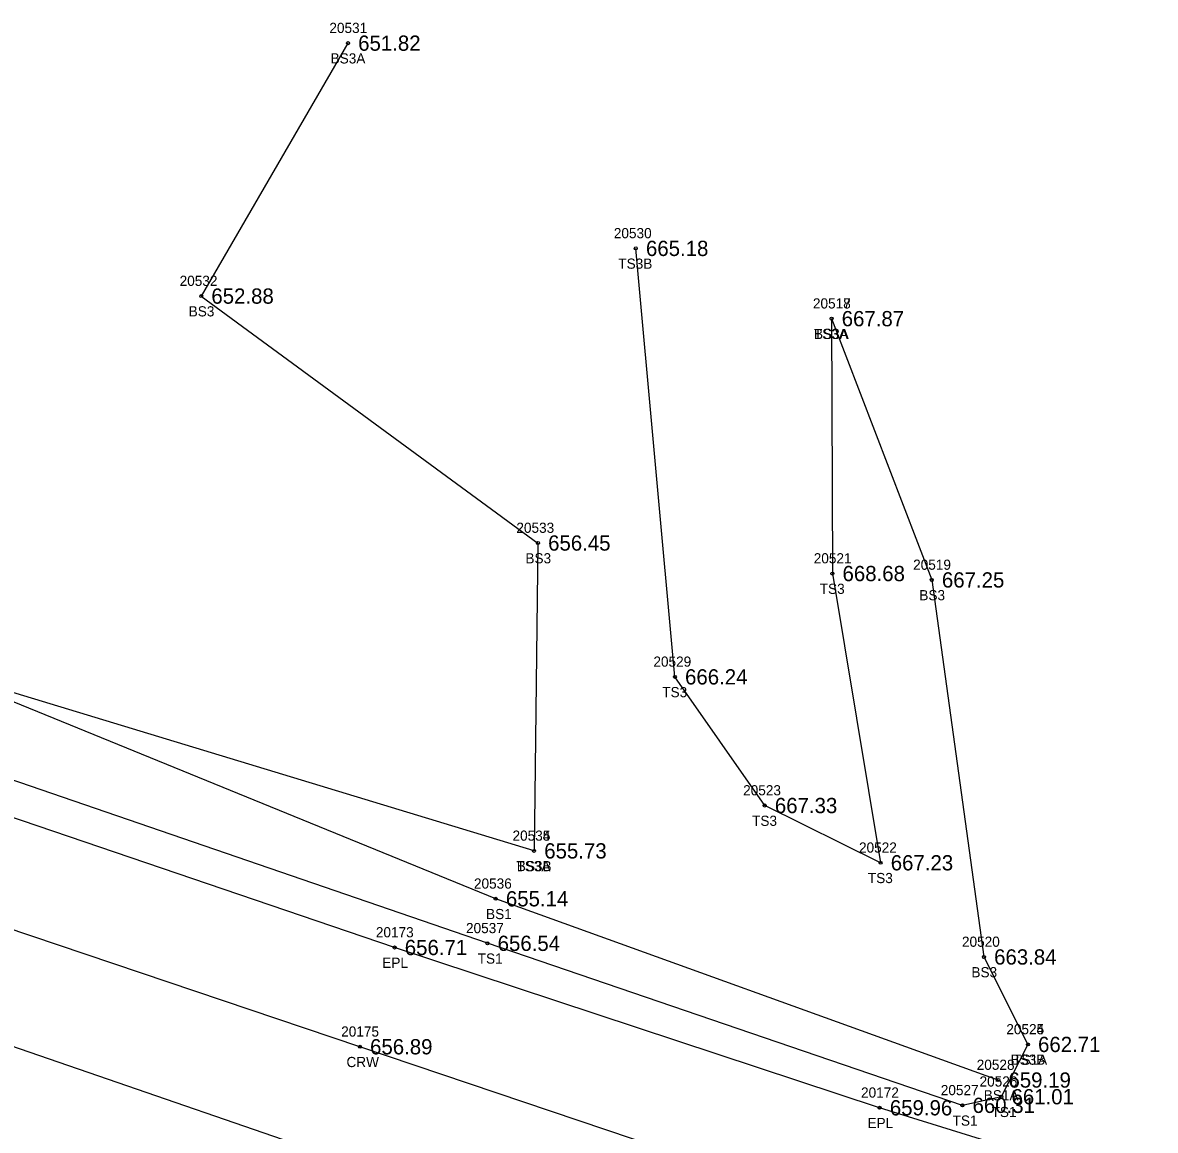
# Model space of a CAD drawing. Extents: x 1655675 to 1657082, y 1004080 to 1005193.
# Drawn here: x 1656444.9 to 1656556.3, y 1004582.5 to 1004691.4 of the extents above; entities that cross this region are included whole.
import ezdxf

# ---------------------------------------------------------------- set-up
doc = ezdxf.new("R2010")
doc.units = 0
for name, color, linetype in [('RD_DTM_BkLn1', 7, 'Continuous'), ('RD_DTM_BkLn2', 7, 'Continuous'), ('RD_DTM_BkLn_txCode', 7, 'Continuous'), ('RD_EX_Road', 7, 'Continuous'), ('RD_EX_Road_txCode', 7, 'Continuous'), ('RD_EX_TX_Misc_ELEV', 7, 'Continuous'), ('RD_EX_TX_Road_ELEV', 7, 'Continuous'), ('RD_HC_Survey_ELEV', 7, 'Continuous'), ('RD_HC_Survey_txCode', 7, 'Continuous'), ('RD_SMD_Locator', 7, 'Continuous')]:
    doc.layers.add(name, color=color, linetype=linetype)

msp = doc.modelspace()

# ---------------------------------------------------------------- linework, layer by layer
at = {"layer": 'RD_DTM_BkLn1'}
msp.add_lwpolyline([(1657061.44, 1004399.53), (1657012.07, 1004414.01), (1656963.11, 1004429.39), (1656914.21, 1004444.93), (1656865.73, 1004460.97), (1656817.07, 1004476.94), (1656768.62, 1004493.15), (1656720.24, 1004509.39), (1656671.72, 1004525.86), (1656623.45, 1004542.51), (1656574.61, 1004558.72), (1656526.43, 1004574.41), (1656478.09, 1004590.75), (1656429.6, 1004607.09), (1656401.58, 1004616.48)], dxfattribs=at)
at = {"layer": 'RD_DTM_BkLn2'}
msp.add_line((1656495.21, 1004610.01), (1656435.31, 1004628.2), dxfattribs=at)
for points in [[(1656476.92, 1004689.43), (1656462.49, 1004664.56), (1656495.59, 1004640.28), (1656495.21, 1004610.01)], [(1656524.45, 1004662.34), (1656524.53, 1004637.28), (1656529.27, 1004608.84), (1656517.88, 1004614.47), (1656509.05, 1004627.12), (1656505.21, 1004669.25)], [(1656524.45, 1004662.34), (1656534.3, 1004636.65), (1656539.43, 1004599.58), (1656543.75, 1004590.98)], [(1656540.84, 1004587.48), (1656491.44, 1004605.3), (1656435.31, 1004628.2), (1656397.73, 1004643.7), (1656383.79, 1004647.24)], [(1656543.75, 1004590.98), (1656541.14, 1004585.84), (1656537.31, 1004584.99), (1656490.63, 1004600.92), (1656432.8, 1004620.8), (1656433.99, 1004621.11), (1656408.04, 1004631.78), (1656404.96, 1004629.91)]]:
    msp.add_lwpolyline(points, dxfattribs=at)
at = {"layer": 'RD_EX_Road'}
for points in [[(1657064.39, 1004409.09), (1657015.67, 1004424.64), (1656965.82, 1004440.6), (1656917.99, 1004455.95), (1656868.5, 1004471.86), (1656826.53, 1004486.06), (1656801.74, 1004494.51), (1656772.14, 1004504.27), (1656723.45, 1004520.92), (1656674.94, 1004537.34), (1656626.5, 1004553.88), (1656578.27, 1004569.52), (1656529.18, 1004584.75), (1656481.5, 1004600.51), (1656432.67, 1004617.14), (1656404.34, 1004625.82)], [(1657057.77, 1004388.92), (1657009.7, 1004404.08), (1656958.18, 1004419.84), (1656956.49, 1004419.67), (1656924.83, 1004429.55), (1656916.51, 1004432.8), (1656911.19, 1004434.68), (1656862.46, 1004450.21), (1656813.53, 1004466.42), (1656765.51, 1004482.33), (1656716.81, 1004499.14), (1656668.6, 1004515.93), (1656620.24, 1004532.54), (1656571.72, 1004548.37), (1656523.3, 1004563.77), (1656474.37, 1004580.29), (1656426.43, 1004596.82), (1656398.22, 1004606.78)]]:
    msp.add_lwpolyline(points, dxfattribs=at)
at = {"layer": 'RD_SMD_Locator'}
for centre in [(1656476.92, 1004689.43), (1656505.21, 1004669.25), (1656462.49, 1004664.56), (1656524.45, 1004662.34), (1656524.45, 1004662.34), (1656495.59, 1004640.28), (1656524.53, 1004637.28), (1656534.3, 1004636.65), (1656509.05, 1004627.12), (1656517.88, 1004614.47), (1656495.21, 1004610.01), (1656495.21, 1004610.01), (1656529.27, 1004608.84), (1656491.44, 1004605.3), (1656481.5, 1004600.51), (1656490.63, 1004600.92), (1656539.43, 1004599.58), (1656543.75, 1004590.98), (1656543.75, 1004590.98), (1656478.09, 1004590.75), (1656540.84, 1004587.48), (1656541.14, 1004585.84), (1656529.18, 1004584.75), (1656537.31, 1004584.99)]:
    msp.add_circle(centre, 0.15, dxfattribs=at)

# ---------------------------------------------------------------- texts
at = {"layer": 'RD_DTM_BkLn_txCode'}
for s, p in [('20531', (1656475.09, 1004690.43)), ('BS3A', (1656475.21, 1004687.43)), ('20530', (1656503.05, 1004670.25)), ('TS3B', (1656503.49, 1004667.25)), ('20532', (1656460.37, 1004665.56)), ('BS3', (1656461.26, 1004662.56)), ('20517', (1656522.62, 1004663.34)), ('20518', (1656522.62, 1004663.34)), ('TS3A', (1656522.72, 1004660.34)), ('BS3A', (1656522.73, 1004660.34)), ('20533', (1656493.47, 1004641.28)), ('BS3', (1656494.36, 1004638.28)), ('20521', (1656522.7, 1004638.28)), ('20519', (1656532.47, 1004637.65)), ('TS3', (1656523.29, 1004635.28)), ('BS3', (1656533.08, 1004634.65)), ('20529', (1656506.94, 1004628.12)), ('TS3', (1656507.81, 1004625.12)), ('20523', (1656515.76, 1004615.47)), ('TS3', (1656516.64, 1004612.47)), ('20534', (1656493.09, 1004611.01)), ('20535', (1656493.09, 1004611.01)), ('20522', (1656527.15, 1004609.84)), ('TS3A', (1656493.48, 1004608.01)), ('BS3B', (1656493.51, 1004608.01)), ('TS3', (1656528.02, 1004606.84)), ('20536', (1656489.3, 1004606.3)), ('BS1', (1656490.49, 1004603.3)), ('20537', (1656488.52, 1004601.92)), ('20520', (1656537.27, 1004600.58)), ('TS1', (1656489.67, 1004598.92)), ('BS3', (1656538.2, 1004597.58)), ('20524', (1656541.63, 1004591.98)), ('20525', (1656541.63, 1004591.98)), ('20528', (1656538.72, 1004588.48)), ('BS3B', (1656542.04, 1004588.98)), ('TS1A', (1656542.3, 1004588.98)), ('20526', (1656539, 1004586.84)), ('20527', (1656535.19, 1004585.99)), ('BS1A', (1656539.41, 1004585.48)), ('TS1', (1656540.18, 1004583.84)), ('TS1', (1656536.35, 1004582.99))]:
    msp.add_text(s, height=1, dxfattribs=at).set_placement(p)
at = {"layer": 'RD_EX_Road_txCode'}
for s, p in [('20173', (1656479.66, 1004601.51)), ('EPL', (1656480.29, 1004598.51)), ('20172', (1656527.35, 1004585.75)), ('EPL', (1656527.98, 1004582.75))]:
    msp.add_text(s, height=1, dxfattribs=at).set_placement(p)
at = {"layer": 'RD_EX_TX_Misc_ELEV'}
for s, p in [('651.82', (1656477.92, 1004688.68)), ('665.18', (1656506.21, 1004668.5)), ('652.88', (1656463.49, 1004663.81)), ('667.87', (1656525.45, 1004661.59)), ('667.87', (1656525.45, 1004661.59)), ('656.45', (1656496.59, 1004639.53)), ('668.68', (1656525.53, 1004636.53)), ('667.25', (1656535.3, 1004635.9)), ('666.24', (1656510.05, 1004626.37)), ('667.33', (1656518.88, 1004613.72)), ('655.73', (1656496.21, 1004609.26)), ('655.73', (1656496.21, 1004609.26)), ('667.23', (1656530.27, 1004608.09)), ('655.14', (1656492.44, 1004604.55)), ('656.54', (1656491.63, 1004600.17)), ('663.84', (1656540.43, 1004598.83)), ('662.71', (1656544.75, 1004590.23)), ('662.71', (1656544.75, 1004590.23)), ('659.19', (1656541.84, 1004586.73)), ('660.31', (1656538.31, 1004584.24)), ('661.01', (1656542.14, 1004585.09))]:
    msp.add_text(s, height=1.5, dxfattribs=at).set_placement(p)
at = {"layer": 'RD_EX_TX_Road_ELEV'}
for s, p in [('656.71', (1656482.5, 1004599.76)), ('659.96', (1656530.18, 1004584))]:
    msp.add_text(s, height=1.5, dxfattribs=at).set_placement(p)
at = {"layer": 'RD_HC_Survey_ELEV'}
msp.add_text('656.89', height=1.5, dxfattribs=at).set_placement((1656479.09, 1004590))
at = {"layer": 'RD_HC_Survey_txCode'}
for s, p in [('20175', (1656476.25, 1004591.75)), ('CRW', (1656476.77, 1004588.75))]:
    msp.add_text(s, height=1, dxfattribs=at).set_placement(p)

doc.saveas('drawing.dxf')
